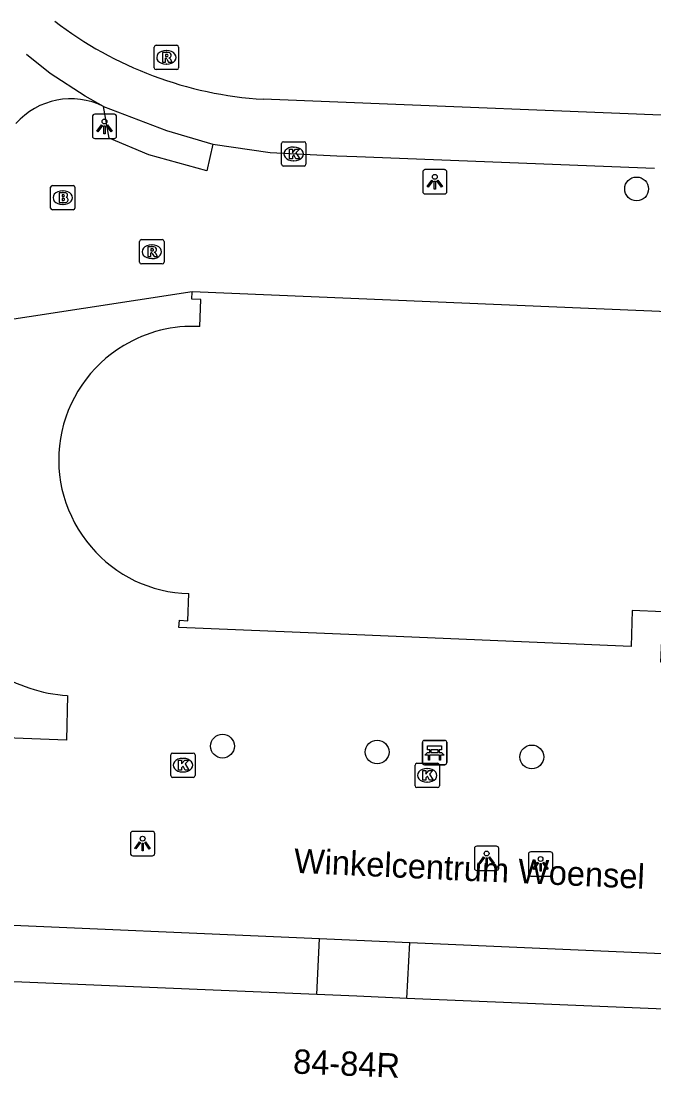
# Model space of a CAD drawing. Extents: x 160891 to 161384, y 386490 to 386907.
# Drawn here: x 160986.22 to 161012.2, y 386863.71 to 386907.15 of the extents above; entities that cross this region are included whole.
import ezdxf

# ---------------------------------------------------------------- set-up
doc = ezdxf.new("R2010")
doc.units = 0
for name, color, linetype in [('IMGEO_Bank', 7, 'Continuous'), ('IMGEO_Boom', 7, 'Continuous'), ('IMGEO_Brandkraan', 7, 'Continuous'), ('IMGEO_Fietspad_open', 7, 'Continuous'), ('IMGEO_Kolk', 7, 'Continuous'), ('IMGEO_Lichtpunt', 7, 'Continuous'), ('IMGEO_Openbare_ruimte_label', 7, 'Continuous'), ('IMGEO_Pand', 7, 'Continuous'), ('IMGEO_Pand_nummerreeks', 7, 'Continuous'), ('IMGEO_Rijbaan_lokaal_gesloten', 7, 'Continuous'), ('IMGEO_Rioolput', 7, 'Continuous'), ('IMGEO_Voetpad_open', 7, 'Continuous')]:
    doc.layers.add(name, color=color, linetype=linetype)

msp = doc.modelspace()

# ---------------------------------------------------------------- linework, layer by layer
at = {"layer": 'IMGEO_Bank'}
for p, q in [((161002.695, 386876.655), (161002.695, 386877.496)), ((161002.695, 386877.496), (161002.695, 386876.655)), ((161002.77, 386877.58), (161003.611, 386877.58)), ((161003.611, 386877.58), (161002.77, 386877.58)), ((161003.004, 386877.086), (161003.004, 386877.192)), ((161003.048, 386877.192), (161003.048, 386877.086)), ((161003.336, 386877.198), (161003.054, 386877.198)), ((161003.342, 386877.086), (161003.342, 386877.192)), ((161003.386, 386877.192), (161003.386, 386877.086)), ((161003.695, 386877.505), (161003.695, 386876.664)), ((161003.695, 386876.664), (161003.695, 386877.505)), ((161003.392, 386876.978), (161002.999, 386876.978)), ((161003.054, 386877.08), (161003.336, 386877.08)), ((161003.62, 386876.58), (161002.779, 386876.58)), ((161002.779, 386876.58), (161003.62, 386876.58))]:
    msp.add_line(p, q, dxfattribs=at)
for points in [[(161002.998, 386877.198), (161002.912, 386877.198), (161002.912, 386877.359), (161003.475, 386877.359), (161003.475, 386877.198), (161003.392, 386877.198)], [(161002.942, 386876.978), (161002.8, 386876.978), (161002.912, 386877.08), (161002.998, 386877.08)], [(161002.992, 386876.971), (161002.992, 386876.764), (161002.949, 386876.764), (161002.949, 386876.971)], [(161003.392, 386877.08), (161003.475, 386877.08), (161003.587, 386876.978), (161003.448, 386876.978)], [(161003.442, 386876.971), (161003.442, 386876.764), (161003.398, 386876.764), (161003.398, 386876.971)]]:
    msp.add_lwpolyline(points, dxfattribs=at)
for centre, radius, start, end in [((161002.773, 386877.502), 0.0779, 92.4484, 184.2845), ((161002.773, 386877.502), 0.0779, 92.4484, 184.2845), ((161002.997, 386877.191), 0.00671, 2.8957, 87.1043), ((161003.054, 386877.191), 0.00671, 92.8957, 177.1043), ((161003.336, 386877.191), 0.00671, 2.8957, 87.1043), ((161003.393, 386877.191), 0.00671, 92.8957, 177.1043), ((161003.617, 386877.502), 0.0779, 2.4484, 94.2845), ((161003.617, 386877.502), 0.0779, 2.4484, 94.2845), ((161002.942, 386876.971), 0.00671, 2.8957, 87.1043), ((161002.999, 386876.971), 0.00671, 92.8957, 177.1043), ((161002.997, 386877.087), 0.00671, 272.8957, 357.1043), ((161003.054, 386877.087), 0.00671, 182.8957, 267.1043), ((161003.336, 386877.087), 0.00671, 272.8957, 357.1043), ((161003.393, 386877.087), 0.00671, 182.8957, 267.1043), ((161003.391, 386876.971), 0.00671, 2.8957, 87.1043), ((161003.448, 386876.971), 0.00671, 92.8957, 177.1043), ((161002.773, 386876.658), 0.0779, 182.4484, 274.2845), ((161002.773, 386876.658), 0.0779, 182.4484, 274.2845), ((161003.617, 386876.658), 0.0779, 272.4484, 4.2845), ((161003.617, 386876.658), 0.0779, 272.4484, 4.2845)]:
    msp.add_arc(centre, radius, start, end, dxfattribs=at)
at = {"layer": 'IMGEO_Boom'}
for centre in [(161011.496, 386900.25), (160994.484, 386877.344), (161000.837, 386877.102), (161007.19, 386876.899)]:
    msp.add_circle(centre, 0.489, dxfattribs=at)
at = {"layer": 'IMGEO_Brandkraan'}
for p, q in [((160987.426, 386899.465), (160987.426, 386900.317)), ((160987.501, 386900.391), (160988.353, 386900.391)), ((160988.427, 386900.317), (160988.427, 386899.465)), ((160987.914, 386900.171), (160987.939, 386900.171)), ((160988.353, 386899.391), (160987.501, 386899.391)), ((160987.937, 386899.611), (160987.912, 386899.611))]:
    msp.add_line(p, q, dxfattribs=at)
for points in [[(160987.426, 386899.465), (160987.426, 386900.317)], [(160987.501, 386900.391), (160988.353, 386900.391)], [(160988.427, 386900.317), (160988.427, 386899.465)], [(160987.774, 386900.091), (160987.774, 386899.691), (160987.987, 386899.691)], [(160988.005, 386900.091), (160987.774, 386900.091)], [(160987.953, 386900.01), (160987.899, 386900.01), (160987.899, 386899.934)], [(160987.899, 386899.934), (160987.952, 386899.934)], [(160987.961, 386899.858), (160987.899, 386899.858), (160987.899, 386899.777)], [(160987.899, 386899.777), (160987.961, 386899.777)], [(160988.353, 386899.391), (160987.501, 386899.391)]]:
    msp.add_lwpolyline(points, dxfattribs=at)
for centre, radius, start, end in [((160987.503, 386900.315), 0.0765, 91.552, 178.448), ((160987.503, 386900.315), 0.0765, 91.552, 178.448), ((160988.351, 386900.315), 0.0765, 1.552, 88.448), ((160988.351, 386900.315), 0.0765, 1.552, 88.448), ((160987.954, 386899.972), 0.0379, 267.8285, 90.9355), ((160987.962, 386899.817), 0.0404, 269.8759, 90.5077), ((160988.009, 386899.946), 0.145, 59.4692, 91.5367), ((160988.034, 386899.993), 0.0922, 285.5137, 58.1501), ((160988.039, 386899.801), 0.105, 301.3115, 78.989), ((160987.503, 386899.467), 0.0765, 181.552, 268.448), ((160987.503, 386899.467), 0.0765, 181.552, 268.448), ((160987.993, 386899.942), 0.251, 268.6676, 293.5347), ((160988.351, 386899.467), 0.0765, 271.552, 358.448), ((160988.351, 386899.467), 0.0765, 271.552, 358.448)]:
    msp.add_arc(centre, radius, start, end, dxfattribs=at)
for centre, major_axis, ratio, start_param, end_param in [((160987.913, 386899.891), (-0.387, 0.002), 0.722429, 4.712389, 7.853982), ((160987.938, 386899.891), (-0.39, 0.002), 0.717154, 1.570796, 4.712389)]:
    msp.add_ellipse(centre, major_axis=major_axis, ratio=ratio, start_param=start_param, end_param=end_param, dxfattribs=at)
at = {"layer": 'IMGEO_Fietspad_open'}
msp.add_arc((160988.262, 386900.942), 3.015, 63.7043, 138.5969, dxfattribs=at)
at = {"layer": 'IMGEO_Kolk'}
for p, q in [((160996.911, 386901.264), (160996.911, 386902.116)), ((160996.986, 386902.19), (160997.838, 386902.19)), ((160997.399, 386901.97), (160997.424, 386901.97)), ((160997.912, 386902.116), (160997.912, 386901.264)), ((160997.838, 386901.19), (160996.986, 386901.19)), ((160997.422, 386901.41), (160997.397, 386901.41)), ((160992.359, 386876.134), (160992.359, 386876.986)), ((160992.434, 386877.06), (160993.286, 386877.06)), ((160992.847, 386876.84), (160992.872, 386876.84)), ((160993.36, 386876.986), (160993.36, 386876.134)), ((161002.393, 386875.714), (161002.393, 386876.566)), ((161002.468, 386876.64), (161003.32, 386876.64)), ((161002.881, 386876.42), (161002.906, 386876.42)), ((161003.394, 386876.566), (161003.394, 386875.714)), ((160993.286, 386876.06), (160992.434, 386876.06)), ((160992.87, 386876.28), (160992.845, 386876.28)), ((161002.904, 386875.86), (161002.879, 386875.86)), ((161003.32, 386875.64), (161002.468, 386875.64))]:
    msp.add_line(p, q, dxfattribs=at)
for points in [[(160996.911, 386901.264), (160996.911, 386902.116)], [(160996.986, 386902.19), (160997.838, 386902.19)], [(160997.912, 386902.116), (160997.912, 386901.264)], [(160997.232, 386901.89), (160997.355, 386901.89), (160997.355, 386901.739), (160997.485, 386901.89), (160997.649, 386901.89), (160997.503, 386901.739), (160997.656, 386901.49), (160997.504, 386901.49), (160997.419, 386901.654), (160997.355, 386901.587), (160997.355, 386901.49), (160997.232, 386901.49), (160997.232, 386901.89)], [(160997.838, 386901.19), (160996.986, 386901.19)], [(160992.359, 386876.134), (160992.359, 386876.986)], [(160992.434, 386877.06), (160993.286, 386877.06)], [(160992.68, 386876.76), (160992.803, 386876.76), (160992.803, 386876.609), (160992.933, 386876.76), (160993.097, 386876.76), (160992.951, 386876.609), (160993.104, 386876.36), (160992.952, 386876.36), (160992.867, 386876.524), (160992.803, 386876.457), (160992.803, 386876.36), (160992.68, 386876.36), (160992.68, 386876.76)], [(160993.36, 386876.986), (160993.36, 386876.134)], [(161002.393, 386875.714), (161002.393, 386876.566)], [(161002.468, 386876.64), (161003.32, 386876.64)], [(161002.714, 386876.34), (161002.837, 386876.34), (161002.837, 386876.189), (161002.967, 386876.34), (161003.131, 386876.34), (161002.985, 386876.189), (161003.138, 386875.94), (161002.986, 386875.94), (161002.901, 386876.104), (161002.837, 386876.037), (161002.837, 386875.94), (161002.714, 386875.94), (161002.714, 386876.34)], [(161003.394, 386876.566), (161003.394, 386875.714)], [(160993.286, 386876.06), (160992.434, 386876.06)], [(161003.32, 386875.64), (161002.468, 386875.64)]]:
    msp.add_lwpolyline(points, dxfattribs=at)
for centre, start, end in [((160996.988, 386902.114), 91.552, 178.448), ((160996.988, 386902.114), 91.552, 178.448), ((160997.836, 386902.114), 1.552, 88.448), ((160997.836, 386902.114), 1.552, 88.448), ((160996.988, 386901.266), 181.552, 268.448), ((160996.988, 386901.266), 181.552, 268.448), ((160997.836, 386901.266), 271.552, 358.448), ((160997.836, 386901.266), 271.552, 358.448), ((160992.436, 386876.984), 91.552, 178.448), ((160992.436, 386876.984), 91.552, 178.448), ((160993.284, 386876.984), 1.552, 88.448), ((160993.284, 386876.984), 1.552, 88.448), ((161002.47, 386876.564), 91.552, 178.448), ((161002.47, 386876.564), 91.552, 178.448), ((161003.318, 386876.564), 1.552, 88.448), ((161003.318, 386876.564), 1.552, 88.448), ((160992.436, 386876.136), 181.552, 268.448), ((160992.436, 386876.136), 181.552, 268.448), ((160993.284, 386876.136), 271.552, 358.448), ((160993.284, 386876.136), 271.552, 358.448), ((161002.47, 386875.716), 181.552, 268.448), ((161002.47, 386875.716), 181.552, 268.448), ((161003.318, 386875.716), 271.552, 358.448), ((161003.318, 386875.716), 271.552, 358.448)]:
    msp.add_arc(centre, 0.0765, start, end, dxfattribs=at)
for centre, major_axis, ratio, start_param, end_param in [((160997.398, 386901.69), (-0.387, 0.002), 0.722429, 4.712389, 7.853982), ((160997.423, 386901.69), (-0.39, 0.002), 0.717154, 1.570796, 4.712389), ((160992.846, 386876.56), (-0.387, 0.002), 0.722429, 4.712389, 7.853982), ((160992.871, 386876.56), (-0.39, 0.002), 0.717154, 1.570796, 4.712389), ((161002.88, 386876.14), (-0.387, 0.002), 0.722429, 4.712389, 7.853982), ((161002.905, 386876.14), (-0.39, 0.002), 0.717154, 1.570796, 4.712389)]:
    msp.add_ellipse(centre, major_axis=major_axis, ratio=ratio, start_param=start_param, end_param=end_param, dxfattribs=at)
at = {"layer": 'IMGEO_Lichtpunt'}
for p, q in [((160989.142, 386903.225), (160989.142, 386902.418)), ((160989.142, 386903.225), (160989.142, 386902.418)), ((160990.044, 386903.32), (160989.236, 386903.32)), ((160990.044, 386903.32), (160989.236, 386903.32)), ((160990.138, 386902.418), (160990.138, 386903.225)), ((160990.138, 386902.418), (160990.138, 386903.225)), ((160989.236, 386902.324), (160990.044, 386902.324)), ((160989.236, 386902.324), (160990.044, 386902.324)), ((161002.709, 386900.947), (161002.709, 386900.14)), ((161002.709, 386900.947), (161002.709, 386900.14)), ((161003.611, 386901.042), (161002.803, 386901.042)), ((161003.611, 386901.042), (161002.803, 386901.042)), ((161003.705, 386900.14), (161003.705, 386900.947)), ((161003.705, 386900.14), (161003.705, 386900.947)), ((161002.803, 386900.046), (161003.611, 386900.046)), ((161002.803, 386900.046), (161003.611, 386900.046)), ((160990.705, 386873.741), (160990.705, 386872.934)), ((160990.705, 386873.741), (160990.705, 386872.934)), ((160991.607, 386873.836), (160990.799, 386873.836)), ((160991.607, 386873.836), (160990.799, 386873.836)), ((160991.701, 386872.934), (160991.701, 386873.741)), ((160991.701, 386872.934), (160991.701, 386873.741)), ((160990.799, 386872.84), (160991.607, 386872.84)), ((160990.799, 386872.84), (160991.607, 386872.84)), ((161004.835, 386873.133), (161004.835, 386872.326)), ((161004.835, 386873.133), (161004.835, 386872.326)), ((161005.737, 386873.228), (161004.929, 386873.228)), ((161005.737, 386873.228), (161004.929, 386873.228)), ((161005.831, 386872.326), (161005.831, 386873.133)), ((161005.831, 386872.326), (161005.831, 386873.133)), ((161007.052, 386872.904), (161007.052, 386872.097)), ((161007.052, 386872.904), (161007.052, 386872.097)), ((161007.954, 386872.999), (161007.146, 386872.999)), ((161007.954, 386872.999), (161007.146, 386872.999)), ((161008.048, 386872.097), (161008.048, 386872.904)), ((161008.048, 386872.097), (161008.048, 386872.904)), ((161004.929, 386872.232), (161005.737, 386872.232)), ((161004.929, 386872.232), (161005.737, 386872.232)), ((161007.146, 386872.003), (161007.954, 386872.003)), ((161007.146, 386872.003), (161007.954, 386872.003))]:
    msp.add_line(p, q, dxfattribs=at)
for points in [[(160989.516, 386902.889), (160989.555, 386902.861), (160989.367, 386902.599), (160989.329, 386902.626), (160989.516, 386902.889)], [(160989.618, 386902.841), (160989.665, 386902.841), (160989.665, 386902.519), (160989.618, 386902.519), (160989.618, 386902.841)], [(160989.728, 386902.861), (160989.766, 386902.888), (160989.953, 386902.626), (160989.914, 386902.598), (160989.728, 386902.861)], [(161003.083, 386900.611), (161003.122, 386900.583), (161002.934, 386900.321), (161002.896, 386900.348), (161003.083, 386900.611)], [(161003.185, 386900.563), (161003.232, 386900.563), (161003.232, 386900.241), (161003.185, 386900.241), (161003.185, 386900.563)], [(161003.295, 386900.583), (161003.333, 386900.61), (161003.52, 386900.348), (161003.481, 386900.32), (161003.295, 386900.583)], [(160991.079, 386873.405), (160991.118, 386873.377), (160990.93, 386873.115), (160990.892, 386873.142), (160991.079, 386873.405)], [(160991.181, 386873.357), (160991.228, 386873.357), (160991.228, 386873.035), (160991.181, 386873.035), (160991.181, 386873.357)], [(160991.291, 386873.377), (160991.329, 386873.404), (160991.516, 386873.142), (160991.477, 386873.114), (160991.291, 386873.377)], [(161005.209, 386872.797), (161005.248, 386872.769), (161005.06, 386872.507), (161005.022, 386872.534), (161005.209, 386872.797)], [(161005.311, 386872.749), (161005.358, 386872.749), (161005.358, 386872.427), (161005.311, 386872.427), (161005.311, 386872.749)], [(161005.421, 386872.769), (161005.459, 386872.796), (161005.646, 386872.534), (161005.607, 386872.506), (161005.421, 386872.769)], [(161007.426, 386872.568), (161007.465, 386872.54), (161007.277, 386872.278), (161007.239, 386872.305), (161007.426, 386872.568)], [(161007.528, 386872.52), (161007.575, 386872.52), (161007.575, 386872.198), (161007.528, 386872.198), (161007.528, 386872.52)], [(161007.638, 386872.54), (161007.676, 386872.567), (161007.863, 386872.305), (161007.824, 386872.277), (161007.638, 386872.54)]]:
    msp.add_lwpolyline(points, dxfattribs=at)
for centre in [(160989.641, 386903.023), (161003.208, 386900.745), (160991.204, 386873.539), (161005.334, 386872.931), (161007.551, 386872.702)]:
    msp.add_circle(centre, 0.0994, dxfattribs=at)
for centre, start, end in [((160989.236, 386903.225), 90, 180), ((160989.236, 386903.225), 90, 180), ((160990.044, 386903.225), 0, 90), ((160990.044, 386903.225), 0, 90), ((160989.236, 386902.418), 180, 270), ((160989.236, 386902.418), 180, 270), ((160990.044, 386902.418), 270, 0), ((160990.044, 386902.418), 270, 360), ((161002.803, 386900.947), 90, 180), ((161002.803, 386900.947), 90, 180), ((161003.611, 386900.947), 0, 90), ((161003.611, 386900.947), 0, 90), ((161002.803, 386900.14), 180, 270), ((161002.803, 386900.14), 180, 270), ((161003.611, 386900.14), 270, 0), ((161003.611, 386900.14), 270, 360), ((160990.799, 386873.741), 90, 180), ((160990.799, 386873.741), 90, 180), ((160991.607, 386873.741), 0, 90), ((160991.607, 386873.741), 0, 90), ((160990.799, 386872.934), 180, 270), ((160990.799, 386872.934), 180, 270), ((160991.607, 386872.934), 270, 0), ((160991.607, 386872.934), 270, 360), ((161004.929, 386873.133), 90, 180), ((161004.929, 386873.133), 90, 180), ((161005.737, 386873.133), 0, 90), ((161005.737, 386873.133), 0, 90), ((161007.146, 386872.904), 90, 180), ((161007.146, 386872.904), 90, 180), ((161007.954, 386872.904), 0, 90), ((161007.954, 386872.904), 0, 90), ((161004.929, 386872.326), 180, 270), ((161004.929, 386872.326), 180, 270), ((161005.737, 386872.326), 270, 0), ((161005.737, 386872.326), 270, 360), ((161007.146, 386872.097), 180, 270), ((161007.146, 386872.097), 180, 270), ((161007.954, 386872.097), 270, 0), ((161007.954, 386872.097), 270, 360)]:
    msp.add_arc(centre, 0.0946, start, end, dxfattribs=at)
at = {"layer": 'IMGEO_Pand'}
for points in [[(160993.557, 386894.591), (160993.603, 386895.7), (160993.223, 386895.716), (160993.236, 386896.016)], [(161029.981, 386894.476), (161004.65, 386895.537), (160993.236, 386896.016)], [(161041.618, 386892.502), (161043.434, 386892.427), (161043.44, 386892.556), (161043.741, 386892.544), (161043.277, 386881.267), (161042.977, 386881.279), (161042.983, 386881.409), (161041.31, 386881.494), (161020.328, 386882.383), (161020.255, 386881.065), (161016.978, 386881.201), (161017.026, 386882.693), (161015.75, 386882.733), (161015.686, 386880.661), (161012.496, 386880.789), (161012.587, 386882.859), (161011.314, 386882.915), (161011.271, 386881.437), (161000, 386881.915), (160992.691, 386882.225), (160992.717, 386882.523), (160993.063, 386882.501), (160993.1, 386883.616)], [(160998.354, 386867.127), (160983.947, 386867.733), (160982.879, 386867.778), (160982.977, 386870.114)], [(161002.057, 386866.971), (161000, 386867.058), (160998.354, 386867.127)], [(161040.43, 386865.364), (161023.517, 386866.022), (161022.324, 386866.068), (161022.121, 386866.076), (161022.073, 386864.841), (161017.479, 386865.02), (161017.53, 386866.325), (161016.263, 386866.374), (161002.057, 386866.971)]]:
    msp.add_lwpolyline(points, dxfattribs=at)
for centre, radius, start, end in [((160993.236, 386889.252), 5.349, 86.5601, 121.5901), ((160993.216, 386889.113), 5.457, 120.6453, 220.918), ((160993.225, 386889.015), 5.401, 220.0666, 268.6709)]:
    msp.add_arc(centre, radius, start, end, dxfattribs=at)
at = {"layer": 'IMGEO_Rijbaan_lokaal_gesloten'}
for points in [[(160989.598, 386903.645), (160988.842, 386904.061), (160987.414, 386904.997), (160986.431, 386905.776), (160986.431, 386905.776)], [(161112.299, 386900.982), (161040.205, 386903.901), (161035.665, 386902.345), (160996.157, 386903.935)], [(160989.598, 386903.645), (160992.187, 386902.648), (160994.092, 386902.091)], [(160994.092, 386902.091), (160996.449, 386901.746), (160999.189, 386901.61), (161000, 386901.579), (161012.233, 386901.108)]]:
    msp.add_lwpolyline(points, dxfattribs=at)
msp.add_arc((160997.116, 386919.506), 15.6, 232.3867, 266.4746, dxfattribs=at)
at = {"layer": 'IMGEO_Rioolput'}
for p, q in [((160991.683, 386905.231), (160991.683, 386906.083)), ((160991.758, 386906.157), (160992.61, 386906.157)), ((160992.171, 386905.937), (160992.196, 386905.937)), ((160992.684, 386906.083), (160992.684, 386905.231)), ((160992.61, 386905.157), (160991.758, 386905.157)), ((160992.194, 386905.377), (160992.169, 386905.377)), ((160991.083, 386897.241), (160991.083, 386898.093)), ((160991.158, 386898.167), (160992.01, 386898.167)), ((160992.084, 386898.093), (160992.084, 386897.241)), ((160991.571, 386897.947), (160991.596, 386897.947)), ((160992.01, 386897.167), (160991.158, 386897.167)), ((160991.594, 386897.387), (160991.569, 386897.387))]:
    msp.add_line(p, q, dxfattribs=at)
for points in [[(160991.683, 386905.231), (160991.683, 386906.083)], [(160991.758, 386906.157), (160992.61, 386906.157)], [(160992.272, 386905.855), (160992.02, 386905.857), (160992.02, 386905.457)], [(160992.684, 386906.083), (160992.684, 386905.231)], [(160992.02, 386905.457), (160992.144, 386905.457), (160992.144, 386905.619), (160992.155, 386905.619)], [(160992.198, 386905.776), (160992.144, 386905.776), (160992.144, 386905.695)], [(160992.144, 386905.695), (160992.196, 386905.695)], [(160992.202, 386905.59), (160992.273, 386905.457), (160992.413, 386905.457), (160992.348, 386905.583)], [(160992.61, 386905.157), (160991.758, 386905.157)], [(160991.083, 386897.241), (160991.083, 386898.093)], [(160991.158, 386898.167), (160992.01, 386898.167)], [(160992.084, 386898.093), (160992.084, 386897.241)], [(160991.672, 386897.865), (160991.42, 386897.867), (160991.42, 386897.467)], [(160991.42, 386897.467), (160991.544, 386897.467), (160991.544, 386897.629), (160991.555, 386897.629)], [(160991.598, 386897.786), (160991.544, 386897.786), (160991.544, 386897.705)], [(160991.544, 386897.705), (160991.596, 386897.705)], [(160991.602, 386897.6), (160991.673, 386897.467), (160991.813, 386897.467), (160991.748, 386897.593)], [(160992.01, 386897.167), (160991.158, 386897.167)]]:
    msp.add_lwpolyline(points, dxfattribs=at)
for centre, radius, start, end in [((160991.76, 386906.081), 0.0765, 91.552, 178.448), ((160991.76, 386906.081), 0.0765, 91.552, 178.448), ((160992.271, 386905.745), 0.109, 350.3612, 89.416), ((160992.608, 386906.081), 0.0765, 1.552, 88.448), ((160992.608, 386906.081), 0.0765, 1.552, 88.448), ((160992.154, 386905.566), 0.0533, 26.0293, 88.6989), ((160992.18, 386905.884), 0.19, 274.7715, 282.9687), ((160992.204, 386905.68), 0.0964, 77.0061, 93.1865), ((160992.218, 386905.737), 0.0378, 276.6634, 79.6772), ((160992.269, 386905.745), 0.112, 277.5842, 350.9817), ((160992.253, 386905.53), 0.108, 29.5134, 73.7905), ((160991.76, 386905.233), 0.0765, 181.552, 268.448), ((160991.76, 386905.233), 0.0765, 181.552, 268.448), ((160992.608, 386905.233), 0.0765, 271.552, 358.448), ((160992.608, 386905.233), 0.0765, 271.552, 358.448), ((160991.16, 386898.091), 0.0765, 91.552, 178.448), ((160991.16, 386898.091), 0.0765, 91.552, 178.448), ((160992.008, 386898.091), 0.0765, 1.552, 88.448), ((160992.008, 386898.091), 0.0765, 1.552, 88.448), ((160991.554, 386897.576), 0.0533, 26.0293, 88.6989), ((160991.58, 386897.894), 0.19, 274.7715, 282.9687), ((160991.604, 386897.69), 0.0964, 77.0061, 93.1865), ((160991.618, 386897.747), 0.0378, 276.6634, 79.6772), ((160991.671, 386897.755), 0.109, 350.3612, 89.416), ((160991.669, 386897.755), 0.112, 277.5842, 350.9817), ((160991.653, 386897.54), 0.108, 29.5134, 73.7905), ((160991.16, 386897.243), 0.0765, 181.552, 268.448), ((160991.16, 386897.243), 0.0765, 181.552, 268.448), ((160992.008, 386897.243), 0.0765, 271.552, 358.448), ((160992.008, 386897.243), 0.0765, 271.552, 358.448)]:
    msp.add_arc(centre, radius, start, end, dxfattribs=at)
for centre, major_axis, ratio, start_param, end_param in [((160992.17, 386905.657), (-0.387, 0.002), 0.722429, 4.712389, 7.853982), ((160992.195, 386905.657), (-0.39, 0.002), 0.717154, 1.570796, 4.712389), ((160991.57, 386897.667), (-0.387, 0.002), 0.722429, 4.712389, 7.853982), ((160991.595, 386897.667), (-0.39, 0.002), 0.717154, 1.570796, 4.712389)]:
    msp.add_ellipse(centre, major_axis=major_axis, ratio=ratio, start_param=start_param, end_param=end_param, dxfattribs=at)
at = {"layer": 'IMGEO_Voetpad_open'}
for points in [[(160994.092, 386902.091), (160993.843, 386900.994), (160991.464, 386901.654), (160989.828, 386902.333), (160989.598, 386903.645)], [(160993.236, 386896.016), (160984.295, 386894.643)], [(160988.113, 386879.42), (160988.085, 386877.583), (160973.52, 386878.149)], [(160982.977, 386870.114), (160983.988, 386870.07), (160998.471, 386869.439)], [(160998.354, 386867.127), (160998.471, 386869.439)], [(160998.471, 386869.439), (161000, 386869.372), (161002.18, 386869.277)], [(161002.057, 386866.971), (161002.18, 386869.277)], [(161002.18, 386869.277), (161017.574, 386868.605), (161022.345, 386868.321), (161040.517, 386867.696)]]:
    msp.add_lwpolyline(points, dxfattribs=at)
msp.add_arc((160988.551, 386885.739), 6.334, 237.4467, 266.031, dxfattribs=at)

# ---------------------------------------------------------------- texts
at = {"layer": 'IMGEO_Openbare_ruimte_label'}
msp.add_text('Winkelcentrum Woensel', height=1, rotation=357.3636, dxfattribs=at).set_placement((160997.403, 386872.138))
at = {"layer": 'IMGEO_Pand_nummerreeks'}
msp.add_text('84-84R', height=1, rotation=357.5993, dxfattribs=at).set_placement((160997.372, 386863.887))

doc.saveas('drawing.dxf')
